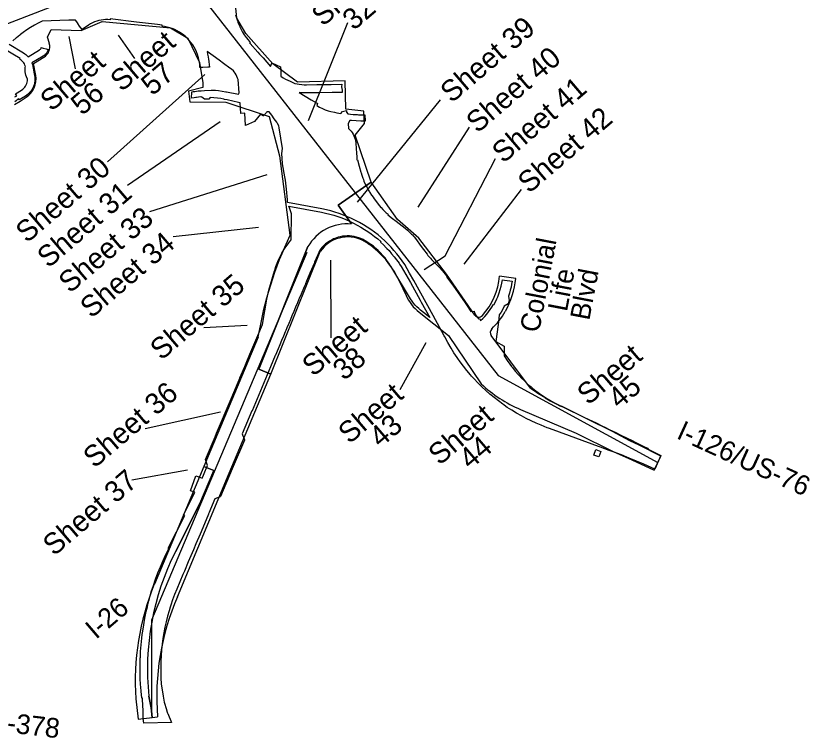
# Model space of a CAD drawing. Extents: x 1944182 to 1978751, y 789830 to 827717.
# Drawn here: x 1964336 to 1976470, y 789830 to 800860 of the extents above; entities that cross this region are included whole.
import ezdxf

# ---------------------------------------------------------------- set-up
doc = ezdxf.new("R2010")
doc.units = 0
for name, color, linetype in [('Default', 7, 'Continuous'), ('RD_AR_01', 7, 'Continuous'), ('RD_AR_03', 7, 'Continuous'), ('RD_SHT_ID', 7, 'Continuous'), ('RD_SHT_Misc4', 7, 'Continuous')]:
    doc.layers.add(name, color=color, linetype=linetype)

msp = doc.modelspace()

# ---------------------------------------------------------------- linework, layer by layer
at = {"layer": 'Default'}
for points in [[(1967693, 800878), (1967705, 800831), (1967706, 800828), (1967720, 800785), (1967728, 800764), (1967737, 800740), (1967755, 800696), (1967758, 800691), (1967777, 800652), (1967800, 800610), (1967825, 800569), (1967839, 800549), (1967853, 800530), (1967882, 800492), (1967913, 800455), (1967906, 800448), (1967913, 800440), (1968034, 800304), (1968060, 800275), (1968112, 800217), (1968228, 800087), (1968244, 800138), (1968245, 800140), (1968245, 800141), (1968380, 800081), (1968381, 800033), (1968382, 799943), (1968382, 799940), (1968385, 799937), (1968419, 799915), (1968454, 799895), (1968490, 799877), (1968528, 799861), (1968596, 799829), (1968631, 799821), (1968666, 799815), (1968702, 799810), (1968738, 799808), (1968764, 799808), (1968774, 799808), (1968934, 799810), (1968985, 799811), (1969151, 799814), (1969314, 799816), (1969308, 799777), (1969319, 799727), (1969320, 799691), (1969170, 799689), (1968967, 799686), (1968872, 799684), (1968776, 799683), (1968739, 799683), (1968701, 799685), (1968664, 799689), (1968849, 799579), (1968937, 799525), (1968944, 799521), (1968932, 799489), (1968975, 799466), (1969018, 799445), (1969063, 799426), (1969109, 799410), (1969147, 799398), (1969203, 799388), (1969239, 799381), (1969298, 799371), (1969328, 799399), (1969385, 799413), (1969388, 799387), (1969388, 799384), (1969390, 799382), (1969409, 799362), (1969489, 799356), (1969547, 799353), (1969569, 799351), (1969649, 799350), (1969665, 799350), (1969673, 799259), (1969674, 799251), (1969611, 799252), (1969604, 799252), (1969533, 799255), (1969463, 799260), (1969439, 799260), (1969412, 799217), (1969418, 799141), (1969438, 799121), (1969456, 799100), (1969473, 799078), (1969488, 799054), (1969500, 799029), (1969511, 799003), (1969520, 798977), (1969526, 798950), (1969530, 798922), (1969530, 798919), (1969536, 798828), (1969540, 798771), (1969540, 798768), (1969544, 798703), (1969546, 798677), (1969547, 798663), (1969555, 798663), (1969582, 798565), (1969606, 798474), (1969610, 798461), (1969620, 798428), (1969636, 798382), (1969644, 798359), (1969653, 798336), (1969673, 798292), (1969687, 798263), (1969695, 798248), (1969718, 798205), (1969737, 798174), (1969743, 798163), (1969770, 798123), (1969797, 798086), (1969799, 798083), (1969857, 798006), (1969892, 797961), (1969912, 797935), (1969915, 797932), (1969940, 797904), (1969966, 797878), (1969976, 797869), (1969993, 797853), (1970022, 797830), (1970016, 797822), (1970091, 797764), (1970143, 797724), (1970285, 797616), (1970319, 797588), (1970351, 797558), (1970382, 797527), (1970394, 797514), (1970411, 797494), (1970418, 797486), (1970418, 797485), (1970439, 797460), (1970439, 797459), (1970529, 797339), (1970564, 797292), (1970618, 797221), (1970631, 797203), (1970649, 797180), (1970668, 797158), (1970687, 797137), (1970795, 797026), (1970854, 796965), (1970875, 796941), (1970894, 796916), (1970912, 796889), (1970927, 796862), (1970952, 796830), (1971021, 796731), (1971198, 796476), (1971229, 796431), (1971288, 796347), (1971338, 796349), (1971339, 796344), (1971344, 796327), (1971350, 796311), (1971351, 796310), (1971360, 796294), (1971401, 796234), (1971418, 796236), (1971436, 796209), (1971468, 796240), (1971499, 796271), (1971529, 796304), (1971557, 796339), (1971583, 796375), (1971607, 796412), (1971621, 796435), (1971630, 796450), (1971639, 796446), (1971662, 796491), (1971684, 796537), (1971697, 796568), (1971704, 796584), (1971720, 796628), (1971721, 796632), (1971736, 796680), (1971749, 796730), (1971750, 796731), (1971760, 796779), (1971769, 796830), (1971802, 796825), (1971802, 796825), (1971881, 796813), (1971917, 796808), (1971910, 796762), (1971900, 796716), (1971889, 796671), (1971877, 796626), (1971862, 796582), (1971873, 796511), (1971857, 796463), (1971857, 796463), (1971798, 796426), (1971774, 796381), (1971748, 796336), (1971721, 796292), (1971707, 796190), (1971687, 796033), (1971667, 795886), (1971793, 795818), (1971793, 795669), (1971840, 795599), (1971880, 795543), (1971907, 795507), (1971921, 795488), (1971964, 795435), (1972009, 795384), (1972033, 795358), (1972034, 795357), (1972056, 795333), (1972057, 795332), (1972059, 795332), (1972060, 795332), (1972060, 795329), (1972104, 795285), (1972154, 795238), (1972206, 795193), (1972225, 795178), (1972259, 795150), (1972313, 795109), (1972369, 795069), (1972427, 795032), (1972423, 795025), (1972500, 794981), (1972578, 794938), (1972658, 794898), (1972662, 794907), (1972678, 794899), (1972973, 794754), (1973025, 794729), (1973200, 794643), (1973290, 794599), (1973335, 794577), (1973412, 794540), (1973489, 794502), (1973590, 794453), (1973752, 794373), (1973797, 794351), (1973951, 794276), (1973992, 794256), (1973993, 794244), (1974190, 794147), (1974096, 793935), (1974041, 793961), (1973930, 794012), (1973918, 794017), (1973817, 794061), (1973704, 794108), (1973590, 794154), (1973475, 794198), (1973400, 794225), (1973335, 794249), (1973333, 794249), (1973267, 794273), (1973236, 794285), (1972546, 794536), (1972471, 794564), (1972453, 794571), (1972360, 794607), (1972283, 794639), (1972207, 794674), (1972132, 794711), (1972058, 794751), (1971985, 794792), (1971913, 794836), (1971843, 794881), (1971797, 794913), (1971790, 794918), (1971774, 794929), (1971707, 794979), (1971641, 795031), (1971576, 795084), (1971513, 795140), (1971452, 795197), (1971393, 795256), (1971335, 795317), (1971298, 795359), (1971280, 795380), (1971226, 795444), (1971174, 795510), (1971124, 795577), (1971087, 795629), (1971075, 795645), (1971029, 795715), (1970986, 795787), (1970936, 795873), (1970888, 795960), (1970881, 795973), (1970711, 796282), (1970417, 796819), (1970351, 796932), (1970276, 797062), (1970238, 797118), (1970198, 797173), (1970156, 797227), (1970112, 797279), (1970067, 797329), (1970019, 797378), (1969970, 797426), (1969920, 797471), (1969868, 797515), (1969814, 797557), (1969759, 797596), (1969702, 797634), (1969645, 797670), (1969586, 797704), (1969526, 797736), (1969464, 797766), (1969402, 797793), (1969339, 797818), (1969275, 797841), (1969210, 797862), (1969145, 797881), (1969079, 797897), (1969012, 797911), (1968486, 798011), (1968484, 798036), (1968483, 798052), (1968469, 798213), (1968457, 798351), (1968444, 798401), (1968408, 798602), (1968407, 798605), (1968398, 798760), (1968408, 798833), (1968360, 799148), (1968354, 799183), (1968334, 799215), (1968320, 799237), (1968284, 799290), (1968247, 799342), (1968207, 799393), (1968168, 799393), (1968163, 799384), (1968119, 799332), (1968114, 799335), (1968074, 799357), (1967980, 799246), (1967845, 799187), (1967832, 799373), (1967772, 799369), (1967760, 799532), (1967738, 799537), (1967565, 799576), (1967523, 799585), (1967512, 799587), (1967469, 799596), (1967415, 799604), (1967361, 799610), (1967306, 799614), (1967281, 799590), (1967256, 799590), (1967217, 799590), (1967178, 799621), (1967166, 799622), (1967159, 799622), (1967124, 799619), (1967097, 799615), (1967084, 799613), (1967061, 799610), (1967019, 799603), (1967022, 799695), (1967021, 799699), (1967043, 799703), (1967069, 799707), (1967118, 799713), (1967130, 799714), (1967166, 799717), (1967215, 799720), (1967321, 799726), (1967376, 799723), (1967383, 799723), (1967432, 799718), (1967487, 799711), (1967541, 799702), (1967554, 799700), (1967736, 799666), (1967748, 799683), (1967732, 799886), (1967723, 799911), (1967713, 799936), (1967701, 799960), (1967688, 799983), (1967672, 800005), (1967661, 800019), (1967629, 800044), (1967604, 800062), (1967507, 800134), (1967441, 800183), (1967260, 800317), (1967262, 800273), (1967272, 800235), (1967280, 800196), (1967284, 800170), (1967286, 800157), (1967291, 800117), (1967293, 800078), (1967268, 800076), (1967190, 800073), (1967148, 800072), (1967145, 800113), (1967140, 800153), (1967133, 800193), (1967125, 800222), (1967123, 800232), (1967110, 800271), (1967095, 800309), (1967078, 800346), (1967059, 800381), (1967037, 800416), (1967014, 800449), (1966988, 800480), (1966963, 800508), (1966961, 800510), (1966938, 800532), (1966931, 800538), (1966901, 800565), (1966868, 800589), (1966834, 800611), (1966799, 800632), (1966763, 800650), (1966725, 800665), (1966687, 800679), (1966648, 800690), (1966608, 800698), (1966568, 800704), (1966570, 800719), (1966501, 800728), (1966180, 800766), (1965778, 800815), (1965776, 800800), (1965741, 800803), (1965739, 800803), (1965707, 800803), (1965672, 800801), (1965638, 800797), (1965604, 800789), (1965570, 800780), (1965538, 800768), (1965506, 800753), (1965476, 800737), (1965447, 800718), (1965349, 800650), (1965310, 800705), (1965281, 800746), (1965281, 800747), (1965246, 800797), (1965143, 800794), (1964737, 800780), (1964715, 800768), (1964677, 800749), (1964618, 800716), (1964560, 800682), (1964503, 800645), (1964447, 800606), (1964408, 800577), (1964394, 800566), (1964345, 800526), (1964341, 800523), (1964290, 800479)], [(1964235, 800428), (1964453, 800295), (1964472, 800282), (1964490, 800268), (1964507, 800252), (1964523, 800236), (1964697, 800340), (1964704, 800345), (1964710, 800351), (1964716, 800358), (1964720, 800366), (1964722, 800375), (1964751, 800369), (1964751, 800369), (1964799, 800357), (1964829, 800348), (1964825, 800335), (1964824, 800330), (1964816, 800313), (1964807, 800297), (1964796, 800282), (1964783, 800268), (1964769, 800256), (1964754, 800246), (1964579, 800141), (1964587, 800116), (1964593, 800089), (1964599, 800059), (1964614, 799977), (1964620, 799947), (1964623, 799919), (1964624, 799891), (1964623, 799863), (1964619, 799836), (1964613, 799809), (1964604, 799782), (1964593, 799757), (1964579, 799732), (1964564, 799709), (1964546, 799688), (1964527, 799668), (1964505, 799650), (1964483, 799634), (1964422, 799596), (1964391, 799576), (1964381, 799592), (1964356, 799577), (1964338, 799563), (1964320, 799548)], [(1964320, 799622), (1964349, 799641), (1964332, 799669), (1964424, 799727), (1964441, 799740), (1964457, 799754), (1964471, 799770), (1964484, 799787), (1964494, 799806), (1964503, 799825), (1964509, 799846), (1964513, 799867), (1964514, 799888), (1964511, 799896), (1964496, 799931), (1964487, 799954), (1964481, 799978), (1964477, 800003), (1964476, 800015), (1964475, 800020), (1964475, 800027), (1964476, 800052), (1964479, 800074), (1964479, 800076), (1964480, 800079), (1964481, 800086), (1964481, 800087), (1964481, 800087), (1964481, 800087), (1964481, 800088), (1964474, 800107), (1964466, 800126), (1964455, 800144), (1964442, 800160), (1964428, 800176), (1964412, 800189), (1964395, 800201), (1964401, 800211), (1964154, 800356)]]:
    msp.add_lwpolyline(points, dxfattribs=at)
for points in [[(1969547, 799360), (1969547, 799356), (1969545, 799356), (1969545, 799358), (1969545, 799360)], [(1969766, 797530), (1969816, 797492), (1969864, 797453), (1969911, 797412), (1969904, 797405), (1969950, 797363), (1969993, 797319), (1970005, 797307), (1970036, 797275), (1970076, 797228), (1970116, 797181), (1970153, 797132), (1970190, 797082), (1970198, 797070), (1970224, 797031), (1970364, 796789), (1970514, 796518), (1970529, 796489), (1970659, 796253), (1970564, 796329), (1970519, 796364), (1970490, 796389), (1970462, 796416), (1970435, 796444), (1970410, 796474), (1970388, 796505), (1970367, 796538), (1970062, 797040), (1970061, 797041), (1970034, 797084), (1970019, 797105), (1970005, 797125), (1969975, 797165), (1969942, 797203), (1969908, 797240), (1969873, 797275), (1969835, 797309), (1969797, 797341), (1969757, 797371), (1969715, 797400), (1969673, 797426), (1969641, 797443), (1969608, 797458), (1969575, 797471), (1969540, 797482), (1969505, 797490), (1969470, 797495), (1969434, 797499), (1969417, 797499), (1969401, 797499), (1969398, 797499), (1969362, 797498), (1969327, 797494), (1969291, 797487), (1969257, 797478), (1969223, 797467), (1969189, 797453), (1969157, 797437), (1969126, 797419), (1969096, 797399), (1969068, 797377), (1969041, 797353), (1969016, 797327), (1968993, 797300), (1968972, 797271), (1968947, 797213), (1968923, 797156), (1968899, 797098), (1968896, 797090), (1968829, 796932), (1968776, 796807), (1968759, 796766), (1968758, 796763), (1968741, 796724), (1968694, 796612), (1968666, 796545), (1968661, 796534), (1968637, 796478), (1968609, 796410), (1968581, 796343), (1968554, 796280), (1968531, 796225), (1968504, 796161), (1968477, 796096), (1968460, 796056), (1968450, 796033), (1968423, 795970), (1968395, 795903), (1968368, 795838), (1968341, 795774), (1968301, 795679), (1968299, 795675), (1968225, 795500), (1967943, 794830), (1967942, 794828), (1967793, 794475), (1967799, 794461), (1967821, 794401), (1967827, 794384), (1967826, 794381), (1967641, 793945), (1967462, 793518), (1967459, 793517), (1967376, 793485), (1967309, 793325), (1967289, 793278), (1967279, 793254), (1967277, 793251), (1967216, 793105), (1967149, 792947), (1967086, 792796), (1967047, 792704), (1967008, 792613), (1966969, 792521), (1966911, 792382), (1966888, 792329), (1966793, 792104), (1966761, 792023), (1966730, 791941), (1966702, 791859), (1966693, 791831), (1966693, 791830), (1966676, 791776), (1966653, 791692), (1966631, 791608), (1966613, 791523), (1966596, 791437), (1966582, 791351), (1966570, 791265), (1966561, 791178), (1966554, 791092), (1966550, 791005), (1966548, 790918), (1966548, 790831), (1966551, 790744), (1966556, 790657), (1966555, 790656), (1966585, 790477), (1966586, 790473), (1966602, 790379), (1966606, 790366), (1966607, 790364), (1966631, 790283), (1966642, 790246), (1966643, 790241), (1966654, 790209), (1966655, 790206), (1966713, 790067), (1966290, 790058), (1966278, 790131), (1966280, 790194), (1966279, 790258), (1966276, 790321), (1966273, 790366), (1966272, 790387), (1966269, 790438), (1966267, 790438), (1966259, 790438), (1966253, 790497), (1966248, 790540), (1966243, 790615), (1966241, 790642), (1966236, 790745), (1966235, 790763), (1966233, 790847), (1966234, 790907), (1966234, 790950), (1966236, 791052), (1966237, 791065), (1966242, 791155), (1966250, 791257), (1966260, 791359), (1966267, 791411), (1966273, 791461), (1966289, 791562), (1966307, 791663), (1966328, 791764), (1966344, 791833), (1966351, 791864), (1966367, 791925), (1966377, 791963), (1966405, 792062), (1966436, 792160), (1966469, 792257), (1966505, 792353), (1966543, 792448), (1966584, 792542), (1966627, 792636), (1966651, 792686), (1966672, 792728), (1966663, 792732), (1966915, 793230), (1966897, 793239), (1966936, 793315), (1966966, 793375), (1966967, 793377), (1967072, 793584), (1967003, 793609), (1967085, 793834), (1967158, 793808), (1967181, 793799), (1967193, 793822), (1967234, 793921), (1967240, 793934), (1967264, 793992), (1967232, 794085), (1967378, 794432), (1967401, 794486), (1967401, 794487), (1967623, 795013), (1967730, 795265), (1967755, 795326), (1967757, 795331), (1967778, 795379), (1967832, 795507), (1967853, 795558), (1967911, 795695), (1967956, 795802), (1968030, 795977), (1968102, 796148), (1968169, 796533), (1968178, 796579), (1968189, 796625), (1968201, 796669), (1968201, 796670), (1968288, 796965), (1968291, 796977), (1968309, 797031), (1968328, 797084), (1968350, 797136), (1968375, 797187), (1968401, 797237), (1968430, 797285), (1968461, 797333), (1968481, 797359), (1968494, 797378), (1968518, 797408), (1968542, 797438), (1968546, 797838), (1968515, 797929), (1968506, 797956), (1969003, 797862), (1969067, 797848), (1969130, 797833), (1969192, 797815), (1969254, 797796), (1969315, 797774), (1969376, 797750), (1969435, 797724), (1969494, 797696), (1969551, 797666), (1969608, 797634), (1969663, 797600), (1969715, 797566)], [(1973270, 794209), (1973240, 794126), (1973166, 794153), (1973196, 794236)]]:
    msp.add_lwpolyline(points, close=True, dxfattribs=at)
at = {"layer": 'RD_AR_01'}
for p, q in [((1969765, 798323), (1969259, 797971)), ((1970167, 797749), (1969765, 798323)), ((1969259, 797971), (1969461, 797682)), ((1970494, 797466), (1970167, 797749)), ((1970913, 796913), (1970494, 797466)), ((1969634, 797430), (1969634, 797430)), ((1969665, 797413), (1969665, 797413)), ((1968232, 795390), (1968984, 797262)), ((1971345, 796290), (1970913, 796913)), ((1971973, 796851), (1971725, 796887)), ((1970198, 796805), (1970297, 796589)), ((1970496, 796335), (1970944, 795977)), ((1970944, 795977), (1971444, 795241)), ((1972196, 795176), (1971596, 795980)), ((1972046, 794848), (1972896, 794486)), ((1973451, 794515), (1972676, 794895)), ((1972896, 794486), (1973473, 794203)), ((1973715, 794372), (1973451, 794515)), ((1973856, 794303), (1973715, 794372)), ((1974190, 794134), (1973856, 794303)), ((1973473, 794203), (1973748, 794082)), ((1973748, 794082), (1974086, 793923)), ((1974086, 793923), (1974190, 794134)), ((1967207, 793980), (1966451, 792179)), ((1967358, 793916), (1967207, 793980)), ((1967146, 793415), (1967358, 793916)), ((1966773, 792677), (1967146, 793415)), ((1966168, 790428), (1966203, 790120)), ((1966401, 790292), (1966369, 790470)), ((1966417, 790144), (1966401, 790292)), ((1966203, 790120), (1966417, 790144))]:
    msp.add_line(p, q, dxfattribs=at)
for points in [[(1968797, 797338), (1968045, 795465), (1968232, 795390)], [(1969634, 797430), (1969634, 797430)], [(1969665, 797413), (1969665, 797413)]]:
    msp.add_lwpolyline(points, dxfattribs=at)
for centre, radius, start, end in [((1969401, 796985), 699, 85.1293, 149.7631), ((1969405, 796974), 510, 63.3443, 145.6266), ((1969405, 796974), 510, 59.3657, 63.3153), ((1969091, 796444), 1126, 59.3527, 59.3657), ((1969091, 796444), 1126, 49.7691, 59.3396), ((1968886, 796202), 1444, 24.6902, 49.7691), ((1970656, 796993), 1075, 318.7062, 354.3338), ((1970656, 796993), 1325, 330.8981, 353.849), ((1970931, 796880), 698, 204.6902, 231.3903), ((1971407, 796333), 75, 214.7587, 318.7062), ((1970830, 796895), 1125, 313.5151, 330.8981), ((1971657, 796025), 75, 133.5151, 216.7171), ((1972852, 796740), 2056, 226.8146, 246.9227), ((1974296, 798204), 3685, 235.2622, 243.9112), ((1970298, 790891), 3952, 153.1374, 186.1179), ((1970134, 790687), 3975, 157.9428, 183.7371)]:
    msp.add_arc(centre, radius, start, end, dxfattribs=at)
at = {"layer": 'RD_AR_03'}
for p, q in [((1967713, 800827), (1967680, 801162)), ((1965331, 800638), (1965652, 800776)), ((1965652, 800776), (1966700, 800676)), ((1967848, 800592), (1967713, 800827)), ((1964819, 800533), (1964875, 800650)), ((1964875, 800650), (1965331, 800638)), ((1966700, 800676), (1966965, 800520)), ((1964847, 800439), (1964819, 800533)), ((1966965, 800520), (1967141, 800147)), ((1968259, 800130), (1967848, 800592)), ((1964606, 800134), (1964764, 800229)), ((1964639, 799950), (1964606, 800134)), ((1967141, 800147), (1967192, 799835)), ((1968639, 799848), (1968259, 800130)), ((1967191, 799765), (1966971, 799710)), ((1967192, 799835), (1967191, 799765)), ((1969366, 799867), (1968639, 799848)), ((1969378, 799433), (1969366, 799867)), ((1966971, 799710), (1966992, 799547)), ((1964312, 799507), (1964402, 799559)), ((1964402, 799559), (1964493, 799617)), ((1966992, 799547), (1967545, 799542)), ((1967545, 799542), (1968205, 799324)), ((1969654, 799404), (1969378, 799433)), ((1969664, 799217), (1969654, 799404)), ((1968205, 799324), (1968363, 798725)), ((1969519, 799037), (1969664, 799217)), ((1969765, 798323), (1969519, 799037)), ((1968363, 798725), (1968523, 797509)), ((1969259, 797971), (1969765, 798323)), ((1969461, 797682), (1969259, 797971)), ((1968035, 795952), (1967207, 793980)), ((1967207, 793980), (1967358, 793916)), ((1967358, 793916), (1967146, 793415)), ((1967146, 793415), (1966773, 792677)), ((1966369, 790470), (1966401, 790292)), ((1966401, 790292), (1966417, 790144)), ((1966417, 790144), (1966501, 790153))]:
    msp.add_line(p, q, dxfattribs=at)
for points in [[(1968232, 795390), (1968045, 795465), (1968797, 797338)], [(1966804, 791988), (1967596, 793875), (1968232, 795390)]]:
    msp.add_lwpolyline(points, dxfattribs=at)
for centre, radius, start, end in [((1964669, 800387), 185, 300.8902, 16.1665), ((1964319, 799892), 325, 302.3152, 10.3499), ((1969401, 796985), 699, 85.1293, 149.7631), ((1973735, 795017), 5777, 154.4533, 170.6847), ((1970298, 790891), 3952, 153.1374, 186.1179), ((1970314, 790466), 3826, 156.5513, 184.6854)]:
    msp.add_arc(centre, radius, start, end, dxfattribs=at)
at = {"layer": 'RD_SHT_ID'}
for p, q in [((1969404, 800755), (1968799, 799259)), ((1965245, 800050), (1965152, 800545)), ((1966154, 800209), (1965902, 800564)), ((1965734, 798633), (1967221, 799963)), ((1970819, 799579), (1969551, 798017)), ((1966040, 798275), (1967458, 799249)), ((1971262, 799161), (1970478, 797937)), ((1970895, 797198), (1971663, 798681)), ((1966383, 797870), (1968176, 798438)), ((1972054, 798210), (1971179, 797070)), ((1966738, 797491), (1968044, 797633)), ((1969154, 795944), (1969147, 797127)), ((1970572, 796986), (1970895, 797198)), ((1967208, 796102), (1967870, 796138)), ((1970205, 795156), (1970604, 795870)), ((1966312, 794561), (1967463, 794815)), ((1966108, 793776), (1966960, 793926))]:
    msp.add_line(p, q, dxfattribs=at)
at = {"layer": 'RD_SHT_Misc4'}
for p, q in [((1964119, 800706), (1968039, 802236)), ((1966734, 801722), (1971705, 795370)), ((1966413, 791638), (1968788, 797250)), ((1971705, 795370), (1974143, 794041)), ((1966413, 790218), (1966413, 791638))]:
    msp.add_line(p, q, dxfattribs=at)

# ---------------------------------------------------------------- texts
at = {"layer": 'RD_SHT_ID'}
for s, height, rotation, p in [('Sheet', 320, 40.5635, (1969026, 800687)), ('32', 320, 40.5635, (1969498, 800627)), ('Sheet 39', 320, 40.5635, (1970993, 799518)), ('Sheet', 320, 40.5635, (1965950, 799690)), ('Sheet 40', 320, 40.5635, (1971387, 799058)), ('Sheet', 320, 40.5635, (1964878, 799389)), ('57', 320, 40.5635, (1966421, 799629)), ('Sheet 41', 320, 40.5635, (1971782, 798597)), ('56', 320, 40.5635, (1965348, 799328)), ('Sheet 42', 320, 40.5635, (1972176, 798137)), ('Sheet 30', 320, 40.5635, (1964505, 797380)), ('Sheet 31', 320, 40.5635, (1964833, 796997)), ('Sheet 33', 320, 40.5635, (1965161, 796613)), ('Sheet 34', 320, 40.5635, (1965489, 796230)), ('Colonial', 300, 79.2018, (1972327, 796011)), ('Life', 300, 79.2018, (1972754, 796333)), ('Blvd', 300, 79.2018, (1973095, 796198)), ('Sheet 35', 320, 40.5635, (1966558, 795588)), ('Sheet', 320, 40.5635, (1968880, 795339)), ('38', 320, 40.5635, (1969350, 795279)), ('Sheet', 320, 40.5635, (1973081, 794903)), ('Sheet 36', 320, 40.5635, (1965536, 793941)), ('45', 320, 40.5635, (1973554, 794845)), ('Sheet', 320, 40.5635, (1969432, 794311)), ('Sheet', 320, 40.5635, (1970809, 793984)), ('43', 320, 40.5635, (1969906, 794253)), ('I-126/US-76', 300, 335.5168, (1974413, 794415)), ('44', 320, 40.5635, (1971277, 793921)), ('Sheet 37', 320, 40.5635, (1964919, 792600)), ('I-26', 300, 40.5635, (1965559, 791329)), ('US-378', 300, 353.2212, (1963637, 789987))]:
    msp.add_text(s, height=height, rotation=rotation, dxfattribs=at).set_placement(p)

doc.saveas('drawing.dxf')
